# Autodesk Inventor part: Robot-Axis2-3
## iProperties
Shininess: 21.0
Length Units: 11269
Angle Units: 11279
Time Units: 11290
Mass Units: 11283
Length Display Precision: 3
Angle Display Precision: 2
Created: 2001-08
Part Number: Robot-Axis2-3
Document SubType Name: ﾓﾃﾞﾘﾝｸﾞ
Designer: Administrator
Density: 1 g/cm^3
Density: 0.0
Volumn: 0.0
Area: 0.0
PropertySet Name: Model Information
Control State: 0
Master: False
Checked Out: False
Author: Administrator
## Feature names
1. 押し出し1 [Extrusion]
2. Fillet
3. Mirror
4. 押し出し2 [Extrusion]
5. Shell1
6. Hole1
7. Hole2
8. Hole3
9. Hole4
